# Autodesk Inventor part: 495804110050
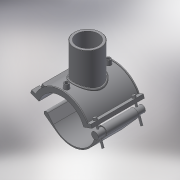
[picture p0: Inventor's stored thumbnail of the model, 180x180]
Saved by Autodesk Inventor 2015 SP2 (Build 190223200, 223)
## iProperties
Created: 2017-07
Part Number: 495804110050
Material: Generic
Description: PLASSON BRANCH SADDLE 110-50
Document SubType Name: Modeling
Designer: KIM
Density: 1 g/cm^3
Appearance: Default
Author: KIM
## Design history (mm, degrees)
derived "495804.ipt"
feature "Solid1::495804.ipt"
feature "Solid2::495804.ipt"
tag "TaggingFeature1"
body "Solid1"
body "Solid2"
other parameters: "d2" = 148, "d3" = 27.5, "d4" = 118, "d5" = 0, "d6" = 0.1, "d8" = 0, "d19" = 6, "d20" = 6, "d21" = 70.8, "d23" = 0, "d24" = 35.4, "d26" = 0, "d27" = 3, "d28" = 3, "d29" = 3, "d30" = 36.66667, "d31" = 6, "d32" = 0, "d33" = 0, "d34" = 0.6, "d40" = 68.64, "d41" = 55, "d43" = 0, "d45" = 0, "d47" = 159, "d50" = 0, "d70" = 15, "d72" = 0, "d73" = 6, "d75" = 5, "d76" = 0, "d77" = 5.5, "d78" = 85, "d79" = 15, "d80" = 47.2, "d82" = 5 deg, "d84" = 4, "d85" = 14, "d86" = 0, "d87" = 3, "d88" = 0, "d89" = 1, "d90" = 1, "d91" = 94.4, "d92" = 0, "d93" = 0.5, "d94" = 57.89474, "d96" = 134.64, "d97" = 2.36, "d98" = 0, "d102" = 1.5, "d105" = 0, "d109" = -31, "d117" = 0.5, "d120" = 140 deg, "d121" = 24.228, "d122" = 20 deg, "d123" = 264, "d124" = 79.2, "d126" = 0, "d143" = 115.5, "d150" = 19.8, "d159" = 4.4, "d161" = 2.75, "d162" = 70.8, "d163" = 0, "d167" = 22, "d173" = 1, "d175" = 55, "d176" = 20 deg, "d177" = 7.7, "d178" = 22, "d180" = 0, "d185" = 38.35, "d186" = 38.35, "d187" = 66, "d188" = 6.6, "d189" = 7.7, "d190" = 0, "d191" = 99, "d200" = 11, "d202" = 0, "d216" = 106.2, "d217" = 0, "d221" = 43.66, "d222" = 7.7, "d223" = 4.62, "d224" = 55, "d225" = 4.62, "d227" = 15.84, "d230" = 68.2, "d236" = 20 deg, "d237" = 73, "d238" = 20 deg, "d239" = 7.7, "B_" = 148, "H_" = 93, "L_" = 118, "d_t" = 6, "H_1" = 82, "d1" = 132, "d148" = 2.75, "d160" = 2.75
